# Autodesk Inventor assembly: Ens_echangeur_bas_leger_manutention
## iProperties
Shininess: 64.0
Length Units: 11269
Angle Units: 11279
Time Units: 11290
Mass Units: 11283
Length Display Precision: 3
Angle Display Precision: 2
Compacted: True
Created: 2008-03
Part Number: Ens_echangeur_bas_leger_manutention
Document SubType Name: Assembly
Designer: Pascal
Density: 0.0
Volumn: 0.0
Area: 0.0
PropertySet Name: Model Information
Control State: 0
Master: False
Checked Out: False
DESIGNATION: Echangeur bas
Author: Pascal
